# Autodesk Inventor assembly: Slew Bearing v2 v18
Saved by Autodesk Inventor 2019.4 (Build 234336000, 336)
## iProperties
Created: 2020-05
Part Number: Slew Bearing v2 v18
Document SubType Name: Assembly
Designer: Administrator
Title: Slew Bearing v2 v18 v9
Author: Administrator
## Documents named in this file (5)
- c:\worker\convert-fusion-r04\tmp\job-1\2948\output\files\178587fc-8fac-4631-8e4c-cfe484ac4050\f025e12c-2613-4244-adf8-1cb6a4295fe6.iam
- c:\worker\convert-fusion-r04\tmp\job-1\2948\output\files\178587fc-8fac-4631-8e4c-cfe484ac4050\Rolls A.ipt
- c:\worker\convert-fusion-r04\tmp\job-1\2948\output\files\178587fc-8fac-4631-8e4c-cfe484ac4050\Rolls B.iam
- c:\worker\convert-fusion-r04\tmp\job-1\2948\output\files\178587fc-8fac-4631-8e4c-cfe484ac4050\Race Outer.ipt
- c:\worker\convert-fusion-r04\tmp\job-1\2948\output\files\178587fc-8fac-4631-8e4c-cfe484ac4050\Race Inner.iam
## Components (4 placed, 4 different names)
1. Rolls A:1
2. Rolls B:1 [sub-assembly]
3. Race Outer:1
4. Race Inner:1 [sub-assembly]
